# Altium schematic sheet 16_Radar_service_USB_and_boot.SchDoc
size 289 x 396 mm
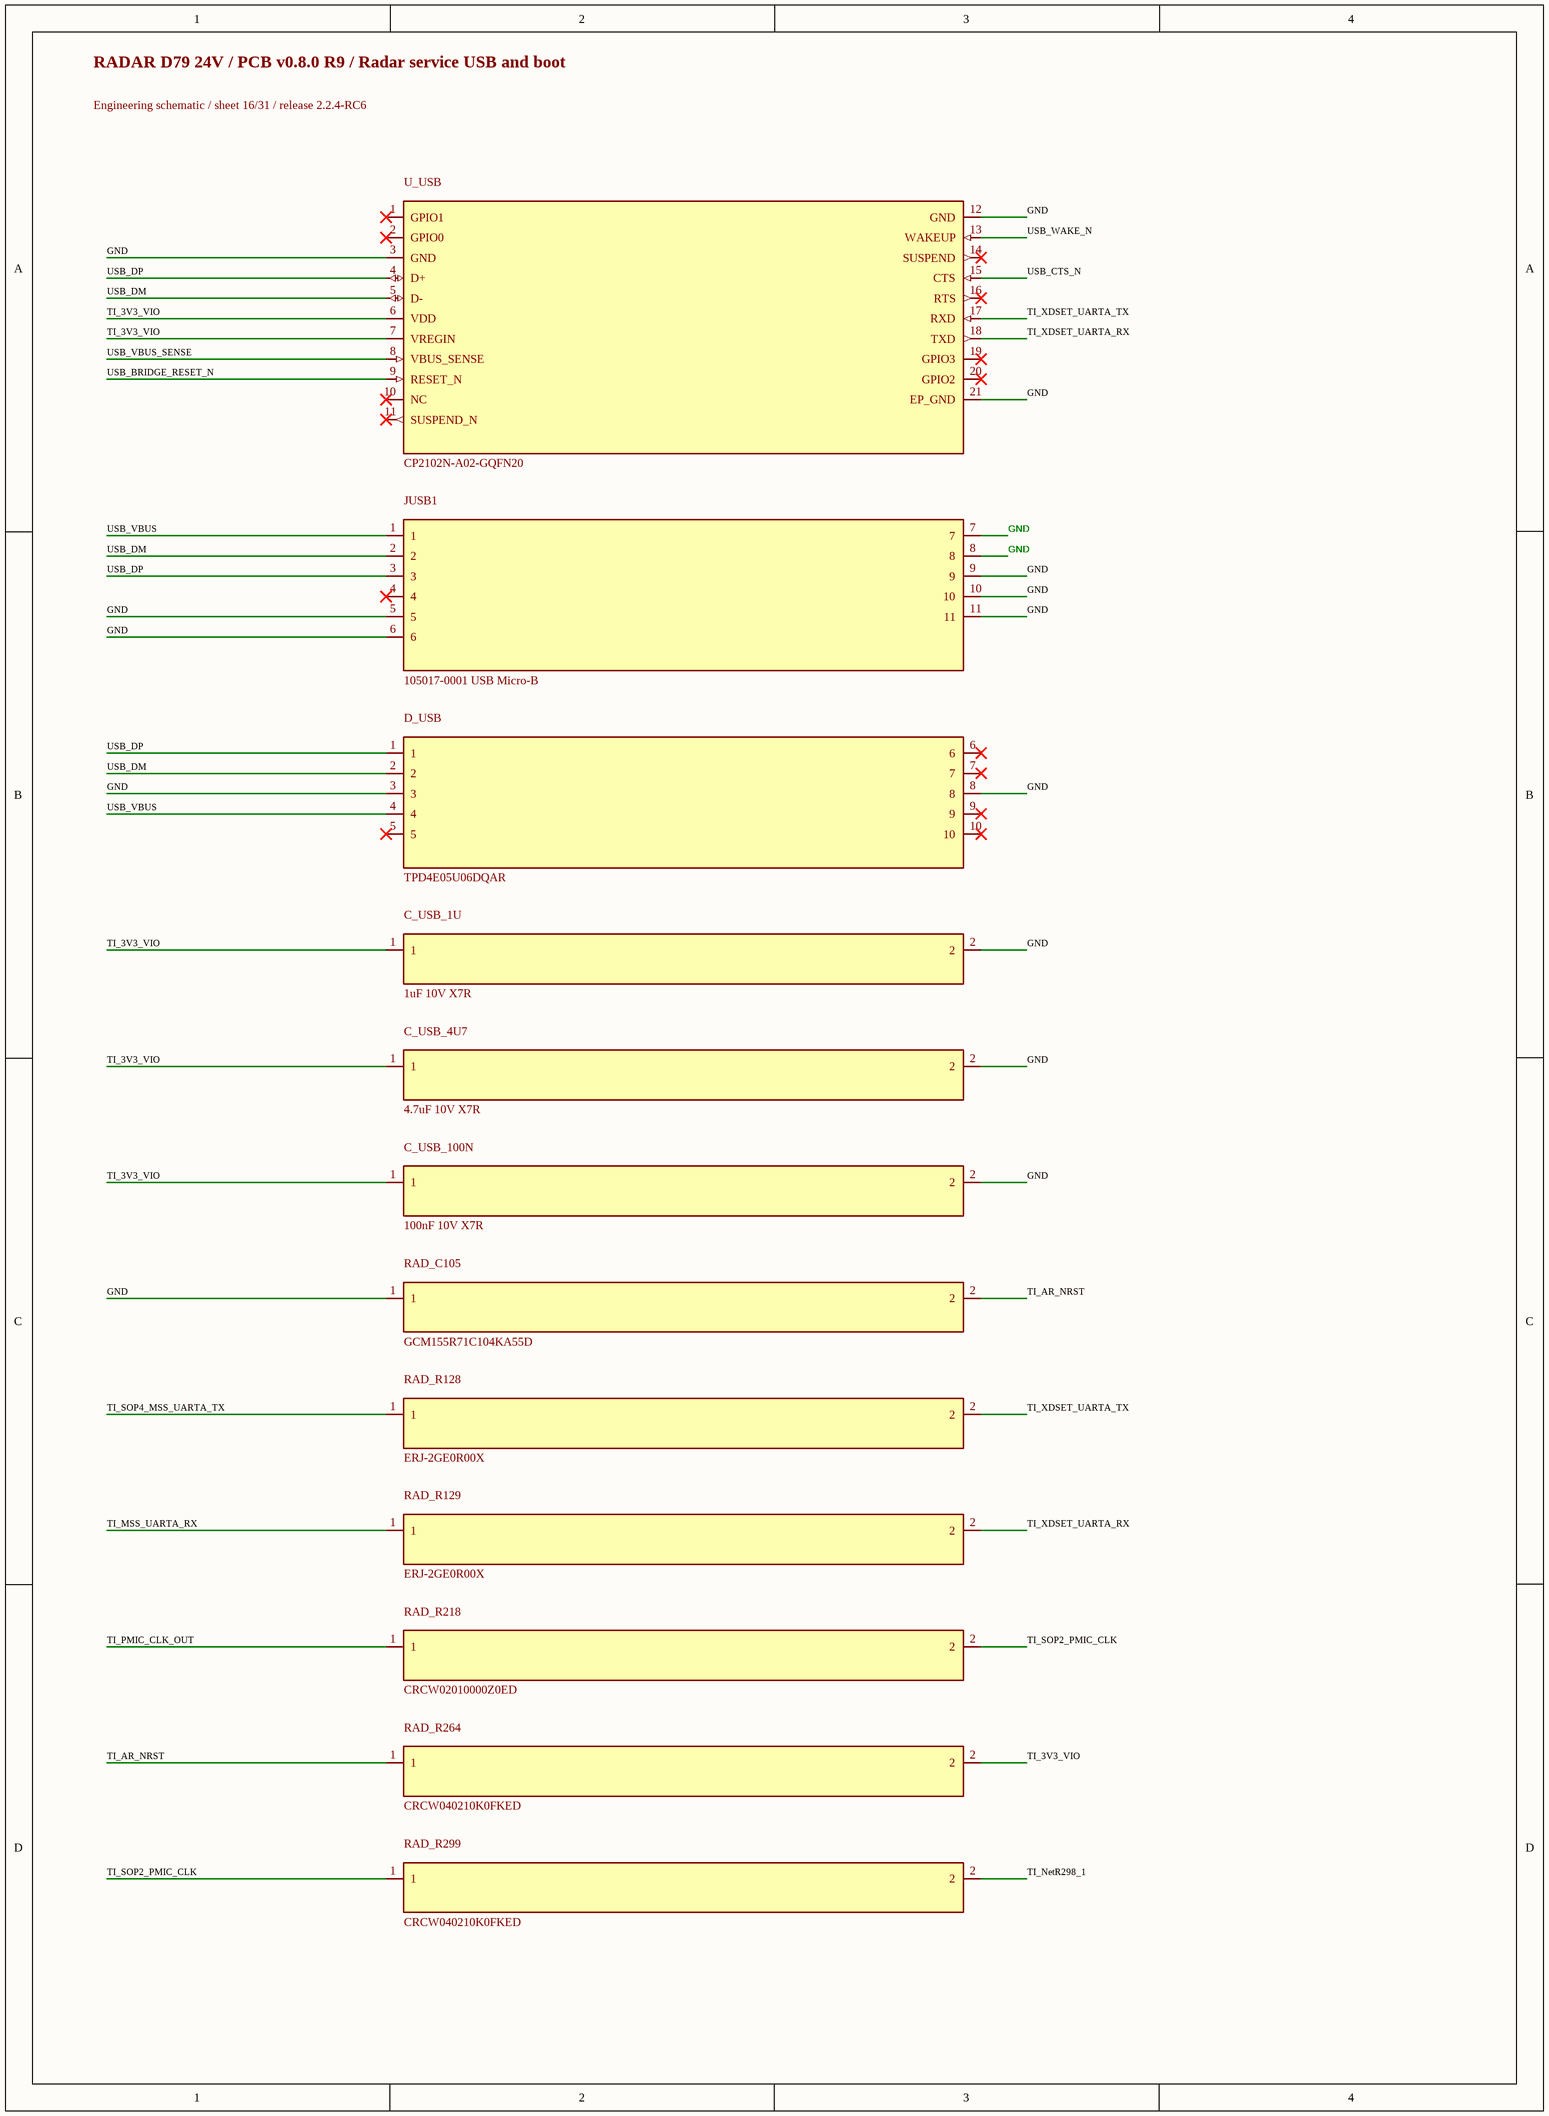
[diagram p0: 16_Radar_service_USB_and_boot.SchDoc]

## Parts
C_USB_1U  1uF 10V X7R  [C_0603_1608Metric]
C_USB_4U7  4.7uF 10V X7R  [C_0603_1608Metric]
C_USB_100N  100nF 10V X7R  [C_0402_1005Metric]
D_USB  TPD4E05U06DQAR  [USON-10_2.5x1.0mm_P0.5mm]
JUSB1  105017-0001 USB Micro-B  [CONN_105017-0001]
RAD_C105  GCM155R71C104KA55D  [0402L]
RAD_R128  ERJ-2GE0R00X  [0402L]
RAD_R129  ERJ-2GE0R00X  [0402L]
RAD_R218  CRCW02010000Z0ED  [0201L]
RAD_R264  CRCW040210K0FKED  [0402L]
RAD_R299  CRCW040210K0FKED  [0402L]
U_USB  CP2102N-A02-GQFN20  [CP2102N_QFN20_3x3_EP_Rev1p5]

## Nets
GND: C_USB_1U.2 C_USB_4U7.2 C_USB_100N.2 D_USB.3 D_USB.8 JUSB1.5 JUSB1.6 JUSB1.7 JUSB1.8 JUSB1.9 JUSB1.10 JUSB1.11 RAD_C105.1 U_USB.3(GND) U_USB.12(GND) U_USB.21(EP_GND)
TI_3V3_VIO: C_USB_1U.1 C_USB_4U7.1 C_USB_100N.1 RAD_R264.2 U_USB.6(VDD) U_USB.7(VREGIN)
TI_AR_NRST: RAD_C105.2 RAD_R264.1
TI_MSS_UARTA_RX: RAD_R129.1
TI_NetR298_1: RAD_R299.2
TI_PMIC_CLK_OUT: RAD_R218.1
TI_SOP2_PMIC_CLK: RAD_R218.2 RAD_R299.1
TI_SOP4_MSS_UARTA_TX: RAD_R128.1
TI_XDSET_UARTA_RX: RAD_R129.2 U_USB.18(TXD)
TI_XDSET_UARTA_TX: RAD_R128.2 U_USB.17(RXD)
USB_BRIDGE_RESET_N: U_USB.9(RESET_N)
USB_CTS_N: U_USB.15(CTS)
USB_DM: D_USB.2 JUSB1.2 U_USB.5(D-)
USB_DP: D_USB.1 JUSB1.3 U_USB.4(D+)
USB_VBUS: D_USB.4 JUSB1.1
USB_VBUS_SENSE: U_USB.8(VBUS_SENSE)
USB_WAKE_N: U_USB.13(WAKEUP)

Not connected (* = marked no-connect by the designer): D_USB 5* 6* 7* 9* 10*; JUSB1 4*; U_USB 1(GPIO1)* 2(GPIO0)* 10(NC)* 11(SUSPEND_N)* 14(SUSPEND)* 16(RTS)* 19(GPIO3)* 20(GPIO2)*

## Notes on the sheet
- RADAR D79 24V / PCB v0.8.0 R9 / Radar service USB and boot
- Engineering schematic / sheet 16/31 / release 2.2.4-RC6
